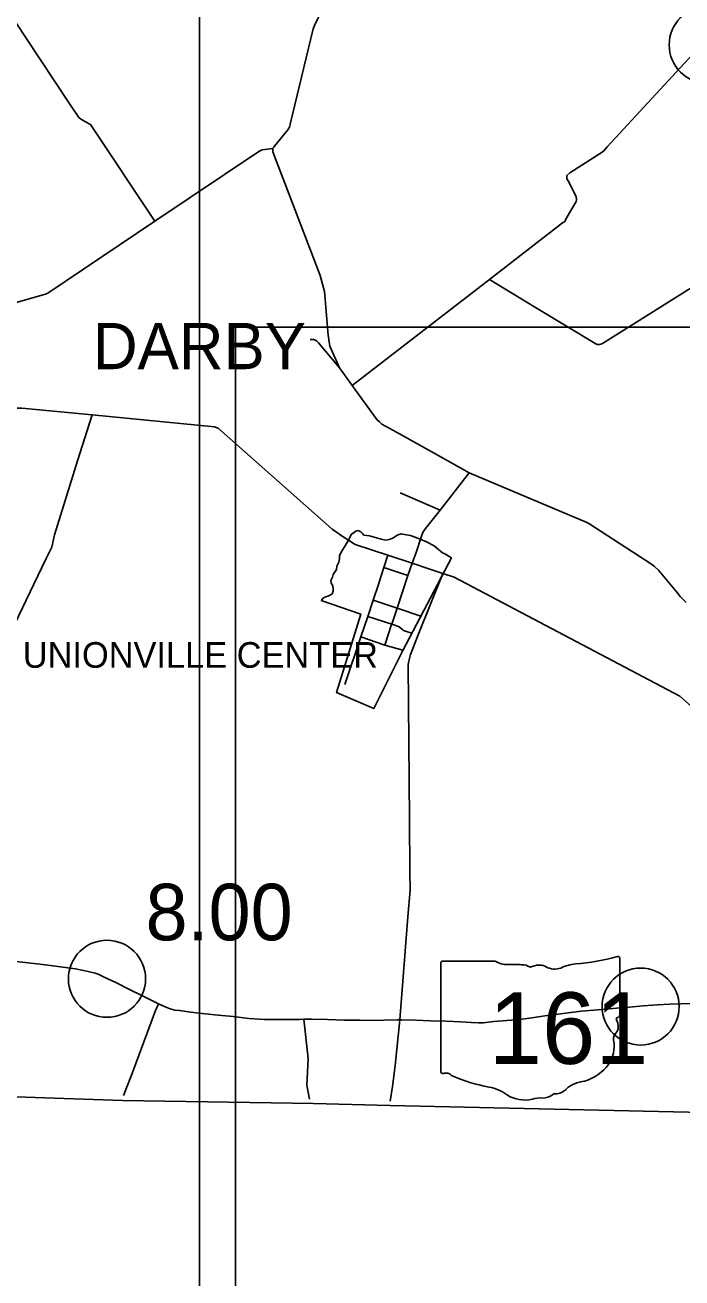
# Model space of a CAD drawing. Extents: x 1659811 to 1934326, y 644115 to 934867.
# Drawn here: x 1726199 to 1738979, y 766164 to 790558 of the extents above; entities that cross this region are included whole.
import ezdxf

# ---------------------------------------------------------------- set-up
doc = ezdxf.new("R2010")
doc.units = 0
for name, color, linetype in [('Default', 7, 'Continuous'), ('GM_X_City_Street', 7, 'Continuous'), ('GM_X_Corporation', 7, 'Continuous'), ('GM_X_Corporation_Text', 7, 'Continuous'), ('GM_X_County', 7, 'Continuous'), ('GM_X_County_Road', 7, 'Continuous'), ('GM_X_State_Route', 7, 'Continuous'), ('GM_X_State_Shield', 7, 'Continuous'), ('GM_X_Township_Road', 7, 'Continuous'), ('GM_X_Township_Text', 7, 'Continuous'), ('SC_Scratch1', 7, 'Continuous')]:
    doc.layers.add(name, color=color, linetype=linetype)

msp = doc.modelspace()

# ---------------------------------------------------------------- linework, layer by layer
at = {"layer": 'Default'}
for centre in [(1739481, 790172), (1727793, 771988), (1738176, 771448)]:
    msp.add_circle(centre, 750, dxfattribs=at)
at = {"layer": 'GM_X_City_Street'}
for points in [[(1732489, 780528), (1732490, 780527), (1732624, 780445)], [(1732624, 780445), (1732624, 780444), (1733259, 780234), (1733728, 780080)], [(1733728, 780080), (1733808, 780289), (1733904, 780584), (1733906, 780590)], [(1733083, 779690), (1733083, 779693), (1733182, 779997), (1733259, 780234)], [(1733182, 779997), (1733649, 779843)], [(1733437, 779205), (1733649, 779843), (1733728, 780080)], [(1734076, 779962), (1733728, 780080)], [(1734325, 779878), (1734076, 779962), (1734076, 779962)], [(1732418, 777719), (1732733, 778647), (1732865, 779040), (1732972, 779360), (1733080, 779683), (1733083, 779690)], [(1732972, 779360), (1733436, 779203), (1733459, 779195)], [(1733334, 778896), (1733431, 779187), (1733436, 779203), (1733437, 779205)], [(1733459, 779195), (1733459, 779195), (1733898, 779047)], [(1732865, 779040), (1733332, 778891), (1733354, 778884), (1733356, 778884)], [(1733197, 778484), (1733330, 778886), (1733332, 778891), (1733334, 778896)], [(1733356, 778884), (1733467, 778849), (1733481, 778843), (1733555, 778778), (1733563, 778770), (1733603, 778760), (1733726, 778716)], [(1732733, 778647), (1733197, 778484), (1733551, 778385)]]:
    msp.add_lwpolyline(points, dxfattribs=at)
at = {"layer": 'GM_X_Corporation'}
msp.add_lwpolyline([(1731960, 779352), (1732006, 779403), (1732063, 779434), (1732092, 779439), (1732133, 779460), (1732176, 779483), (1732195, 779536), (1732196, 779583), (1732189, 779642), (1732156, 779692), (1732151, 779745), (1732182, 779806), (1732194, 779859), (1732218, 779902), (1732256, 779958), (1732266, 780020), (1732307, 780099), (1732314, 780163), (1732316, 780223), (1732350, 780298), (1732435, 780430), (1732493, 780529), (1732523, 780595), (1732545, 780639), (1732606, 780687), (1732634, 780706), (1732682, 780714), (1732733, 780690), (1732761, 780665), (1732790, 780627), (1732900, 780611), (1732992, 780587), (1733125, 780549), (1733217, 780531), (1733283, 780541), (1733369, 780577), (1733438, 780623), (1733517, 780653), (1733582, 780638), (1733701, 780621), (1733885, 780551), (1734009, 780495), (1734162, 780416), (1734319, 780282), (1734365, 780262), (1734495, 780185), (1733548, 778381), (1732987, 777250), (1732260, 777561), (1732730, 779089)], close=True, dxfattribs=at)
at = {"layer": 'GM_X_County'}
msp.add_lwpolyline([(1739974, 769370), (1733297, 769524), (1731814, 769558), (1728095, 769617), (1723752, 769769)], dxfattribs=at)
at = {"layer": 'GM_X_County_Road'}
for points in [[(1728725, 786741), (1727472, 788619), (1727378, 788673), (1727278, 788730), (1727247, 788761), (1727069, 789021), (1726192, 790343), (1725641, 791181), (1725486, 791417), (1725333, 791731), (1724316, 793882), (1724215, 794049), (1724098, 794240), (1724011, 794380), (1723135, 795771)], [(1739064, 779314), (1738942, 779434), (1738880, 779517), (1738522, 779942), (1738461, 780005), (1738437, 780025), (1738412, 780043), (1738387, 780062), (1737165, 780853), (1737115, 780877), (1737040, 780909), (1734842, 781840), (1734321, 782131), (1733427, 782630), (1733142, 782790), (1733092, 782831), (1733042, 782878), (1732565, 783541), (1732316, 783885), (1732130, 784304), (1732097, 784523), (1732024, 785372), (1731939, 785680), (1731019, 788091), (1731020, 788153), (1731020, 788161), (1731036, 788181), (1731054, 788199), (1731314, 788519), (1731341, 788569), (1731359, 788627), (1731762, 790299), (1731802, 790485), (1731816, 790519), (1731832, 790549), (1732582, 792126)], [(1735233, 785606), (1736656, 786706), (1736696, 786728), (1736749, 786824), (1736919, 787123), (1736931, 787161), (1736921, 787217), (1736763, 787526), (1736737, 787566), (1736739, 787594), (1736738, 787628), (1736798, 787682), (1737427, 788086), (1737464, 788118), (1737525, 788187), (1739424, 790244)], [(1721936, 784478), (1721960, 784498), (1721976, 784506), (1721993, 784512), (1722025, 784518), (1722069, 784493), (1722237, 784411), (1722273, 784400), (1722303, 784391), (1722498, 784331), (1722640, 784311), (1722829, 784324), (1723137, 784361), (1723457, 784391), (1723637, 784431), (1723772, 784474), (1723914, 784552), (1726568, 785311), (1726596, 785321), (1726641, 785338), (1728725, 786741), (1730745, 788099), (1730812, 788131), (1731020, 788153)], [(1735233, 785606), (1736130, 785060), (1737306, 784352), (1737333, 784341), (1737356, 784336), (1737377, 784337), (1737401, 784342), (1737434, 784358), (1739772, 785822)], [(1732565, 783541), (1735233, 785606)], [(1718267, 784543), (1718297, 784517), (1718553, 784303), (1718632, 784252), (1718840, 784182), (1722050, 783178), (1722961, 782860), (1723007, 782847), (1723214, 782846), (1723724, 782926), (1723888, 782988), (1724439, 783080), (1724514, 783096), (1726138, 783099), (1727502, 782967), (1729885, 782734), (1729955, 782707), (1732171, 780744), (1732405, 780579), (1732489, 780528)], [(1724361, 772461), (1724249, 774775), (1724250, 774811), (1724298, 774907), (1724430, 775197), (1724798, 775983), (1725000, 776415), (1725068, 776586), (1725134, 776837), (1725140, 776922), (1725172, 776980), (1725266, 777221), (1725529, 777849), (1725860, 778601), (1726221, 779358), (1726525, 779997), (1726609, 780172), (1726718, 780394), (1726770, 780633), (1727221, 782072), (1727502, 782967)], [(1733946, 780689), (1733989, 780757), (1734275, 781116), (1734842, 781840)], [(1733906, 780590), (1733930, 780665), (1733942, 780684), (1733946, 780689)], [(1733686, 774070), (1733686, 774072), (1733679, 775098), (1733655, 778102), (1733659, 778144), (1733700, 778300), (1733847, 778683), (1734325, 779878)], [(1734325, 779878), (1734550, 779807), (1738937, 777494), (1740161, 776407), (1740191, 776386), (1741765, 775879), (1743383, 774837), (1743414, 774805), (1743951, 774082), (1744158, 773745), (1744523, 773143), (1744960, 772429), (1745098, 772244), (1745512, 771549), (1745705, 771217)], [(1733489, 771191), (1733645, 773196), (1733689, 773714), (1733686, 774070)], [(1733303, 769607), (1733351, 769894), (1733403, 770299), (1733489, 771191)]]:
    msp.add_lwpolyline(points, dxfattribs=at)
at = {"layer": 'GM_X_State_Route'}
msp.add_lwpolyline([(1725798, 772351), (1726201, 772306), (1726599, 772261), (1726932, 772217), (1727180, 772179), (1727425, 772129), (1727565, 772100), (1727622, 772079), (1727751, 772015), (1727966, 771917), (1728228, 771779), (1728484, 771654), (1728668, 771567), (1728797, 771502), (1728928, 771442), (1729024, 771402), (1729115, 771377), (1729201, 771369), (1729427, 771339), (1729703, 771307), (1729958, 771278), (1730246, 771252), (1730550, 771216), (1730753, 771199), (1730843, 771193), (1731004, 771195), (1731250, 771197), (1731536, 771198), (1731623, 771199), (1731774, 771200), (1732084, 771197), (1732399, 771185), (1732719, 771182), (1732931, 771178), (1733171, 771184), (1733439, 771192), (1733489, 771191), (1733531, 771190), (1733796, 771182), (1734088, 771171), (1734390, 771162), (1734672, 771153), (1734876, 771140), (1735022, 771131), (1735112, 771134), (1735318, 771154), (1735573, 771176), (1735827, 771198), (1736058, 771226), (1736315, 771266), (1736572, 771302), (1736816, 771331), (1737017, 771358), (1737268, 771378), (1737486, 771396), (1737704, 771415), (1737961, 771436), (1738224, 771464), (1738502, 771483), (1738743, 771497), (1738967, 771501), (1739281, 771504)], dxfattribs=at)
at = {"layer": 'GM_X_State_Shield'}
for p, q in [((1735344, 772333), (1734325, 772333)), ((1737771, 771280), (1737771, 772385)), ((1734291, 772296), (1734291, 770183)), ((1737771, 771280), (1737771, 771280))]:
    msp.add_line(p, q, dxfattribs=at)
for centre, major_axis, start_param, end_param in [((1734331, 772301), (40.3, 0), 1.712693, 3.28349), ((1735587, 772578), (391, 0), 4.042523, 4.731795), ((1736532, 775214), (3691, 0), 4.814394, 5.042369), ((1737733, 772390), (38.7, 0), 6.141152, 7.989035), ((1735717, 771146), (1404, 0), 1.404758, 1.657858), ((1736036, 772312), (113, 0), 3.836095, 5.185415), ((1736201, 772068), (235, 0), 0.950623, 2.079405), ((1736504, 772403), (282, 0), 4.081561, 5.145723), ((1737002, 771687), (743, 0), 1.699011, 2.107814), ((1737762, 771198), (60, 0), 1.883978, 3.671073), ((1737381, 771059), (360, 0), 5.934695, 6.695948), ((1737730, 771275), (41.5, 0), 5.05454, 6.418171), ((1737910, 770817), (262, 0), 2.387724, 3.262537), ((1736738, 770676), (923, 0), 5.101752, 6.440018), ((1734331, 770178), (40.7, 0), 3.00124, 4.508301), ((1734337, 770395), (310, 0), 4.665946, 4.897461), ((1734401, 770061), (112, 0), 0.519207, 1.627899), ((1735814, 771960), (2665, 0), 4.195997, 4.488961), ((1737128, 769590), (506, 0), 1.647645, 2.488434), ((1735019, 769234), (834, 0), 0.823519, 1.323587), ((1735921, 770051), (529, 0), 4.026481, 4.996735), ((1736227, 769320), (435, 0), 1.495662, 1.94098), ((1736266, 769892), (282, 0), 4.691044, 5.507374), ((1736521, 769688), (79.4, 0), 1.147584, 2.315152), ((1736487, 769978), (298, 0), 4.937069, 5.64225)]:
    msp.add_ellipse(centre, major_axis=major_axis, ratio=0.8, start_param=start_param, end_param=end_param, dxfattribs=at)
at = {"layer": 'GM_X_Township_Road'}
for points in [[(1732316, 783885), (1731909, 784372), (1731867, 784411), (1731817, 784437), (1731745, 784434)], [(1733494, 781452), (1734275, 781116)], [(1728117, 769718), (1728270, 770111), (1728735, 771368), (1728797, 771502)], [(1731730, 769642), (1731683, 769917), (1731709, 770427), (1731692, 770554), (1731623, 771199)]]:
    msp.add_lwpolyline(points, dxfattribs=at)
at = {"layer": 'SC_Scratch1'}
for points in [[(1729596, 899996), (1925846, 899996), (1925846, 765496), (1729596, 765496)], [(1730291, 784675), (1926541, 784675), (1926541, 650175), (1730291, 650175)]]:
    msp.add_lwpolyline(points, close=True, dxfattribs=at)

# ---------------------------------------------------------------- texts
at = {"layer": 'Default'}
msp.add_text('8.00', height=1100, dxfattribs=at).set_placement((1728543, 772738))
at = {"layer": 'GM_X_Corporation_Text'}
msp.add_text('UNIONVILLE CENTER', height=500, rotation=0, dxfattribs=at).set_placement((1726155, 778044))
at = {"layer": 'GM_X_State_Shield'}
msp.add_text('161', height=1392.2, dxfattribs=at).set_placement((1735222, 770332))
at = {"layer": 'GM_X_Township_Text'}
msp.add_text('DARBY', height=900, rotation=0, dxfattribs=at).set_placement((1727519, 783858))

doc.saveas('drawing.dxf')
